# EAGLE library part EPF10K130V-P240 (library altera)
EPF10K130 FLEX 10K family
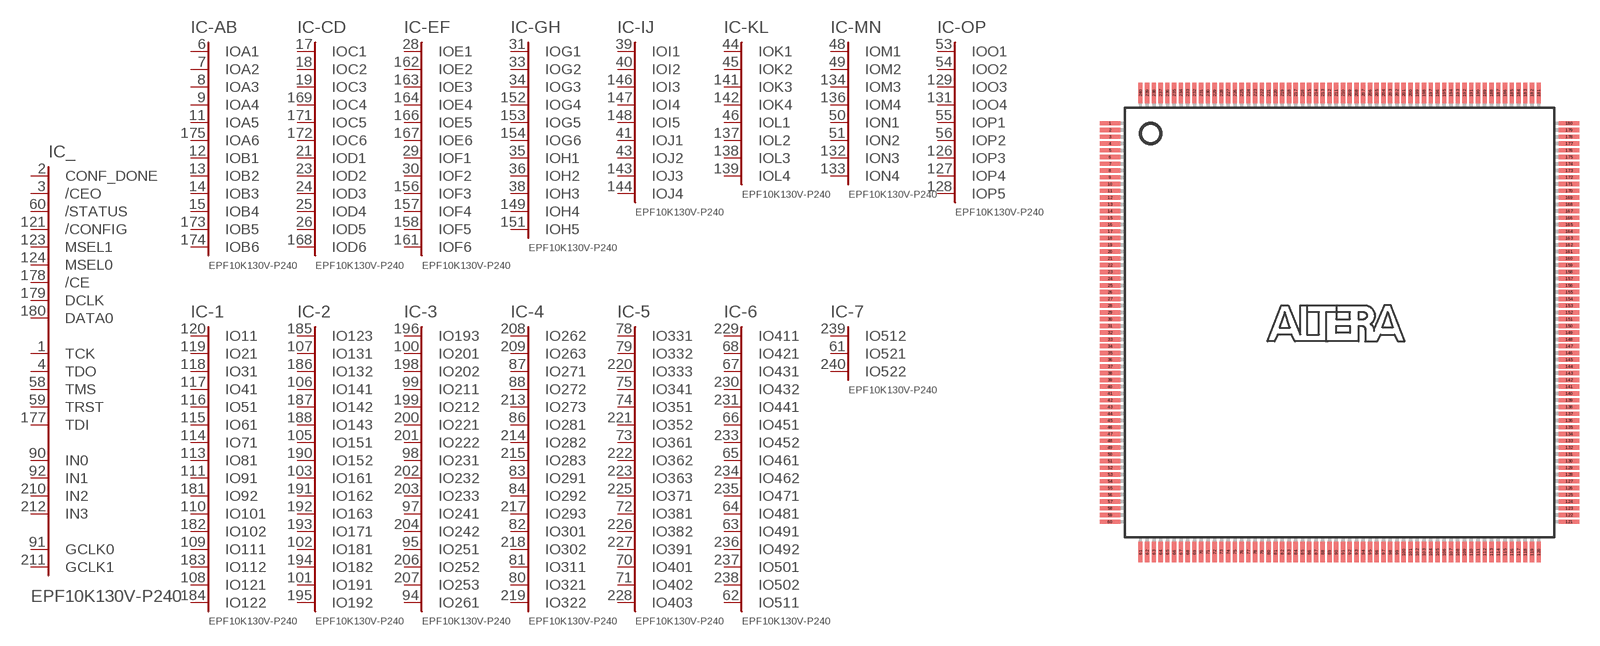
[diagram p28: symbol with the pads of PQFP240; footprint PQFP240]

Designator prefix IC; gates _=K_CTRL -AB=AB6 -CD=CD6 -EF=EF6 -GH=GH6 -IJ=IJ4 -KL=KL4 -MN=MN4 -OP=OP5 -1=122-240 -2=192-240 -3=261-240 -4=322-240 -5=403-240 -6=511-240 -7=522-240 1=VCCINT 2=VCCINT 3=VCCINT 4=VCCINT 5=VCCINT 6=VCCINT 7=VCCINT 8=VCCINT 9=VCCINT 10=VCCINT 11=VCCINT 12=VCCINT 13=VCCIO 14=VCCIO 15=VCCIO 16=VCCIO 17=VCCIO 18=VCCIO 19=VCCIO 20=VCCIO 21=VCCIO 22=VCCIO 23=GND 24=GND 25=GND 26=GND 27=GND 28=GND 29=GND 30=GND 31=GND 32=GND 33=GND 34=GND 35=GND 36=GND 37=GND 38=GND 39=GND 40=GND

## EPF10K130V-P240 (OC_FARNELL: unknown; OC_NEWARK: unknown)  [PQFP240]
1  _:TCK
2  _:CONF_DONE  in
3  _:/CEO  in
4  _:TDO
5  1:VCC  pwr
6  -AB:IOA1
7  -AB:IOA2
8  -AB:IOA3
9  -AB:IOA4
10  23:GND  pwr
11  -AB:IOA5
12  -AB:IOB1
13  -AB:IOB2
14  -AB:IOB3
15  -AB:IOB4
16  13:VCCIO  pwr
17  -CD:IOC1
18  -CD:IOC2
19  -CD:IOC3
20  2:VCC  pwr
21  -CD:IOD1
22  24:GND  pwr
23  -CD:IOD2
24  -CD:IOD3
25  -CD:IOD4
26  -CD:IOD5
27  3:VCC  pwr
28  -EF:IOE1
29  -EF:IOF1
30  -EF:IOF2
31  -GH:IOG1
32  25:GND  pwr
33  -GH:IOG2
34  -GH:IOG3
35  -GH:IOH1
36  -GH:IOH2
37  14:VCCIO  pwr
38  -GH:IOH3
39  -IJ:IOI1
40  -IJ:IOI2
41  -IJ:IOJ1
42  26:GND  pwr
43  -IJ:IOJ2
44  -KL:IOK1
45  -KL:IOK2
46  -KL:IOL1
47  4:VCC  pwr
48  -MN:IOM1
49  -MN:IOM2
50  -MN:ION1
51  -MN:ION2
52  27:GND  pwr
53  -OP:IOO1
54  -OP:IOO2
55  -OP:IOP1
56  -OP:IOP2
57  15:VCCIO  pwr
58  _:TMS
59  _:TRST
60  _:/STATUS  in
61  -7:IO521
62  -6:IO511
63  -6:IO491
64  -6:IO481
65  -6:IO461
66  -6:IO451
67  -6:IO431
68  -6:IO421
69  28:GND  pwr
70  -5:IO401
71  -5:IO402
72  -5:IO381
73  -5:IO361
74  -5:IO351
75  -5:IO341
76  5:VCC  pwr
77  16:VCCIO  pwr
78  -5:IO331
79  -5:IO332
80  -4:IO321
81  -4:IO311
82  -4:IO301
83  -4:IO291
84  -4:IO292
85  29:GND  pwr
86  -4:IO281
87  -4:IO271
88  -4:IO272
89  6:VCC  pwr
90  _:IN0  in
91  _:GCLK0  in
92  _:IN1  in
93  30:GND  pwr
94  -3:IO261
95  -3:IO251
96  7:VCC  pwr
97  -3:IO241
98  -3:IO231
99  -3:IO211
100  -3:IO201
101  -2:IO191
102  -2:IO181
103  -2:IO161
104  31:GND  pwr
105  -2:IO151
106  -2:IO141
107  -2:IO131
108  -1:IO121
109  -1:IO111
110  -1:IO101
111  -1:IO91
112  17:VCCIO  pwr
113  -1:IO81
114  -1:IO71
115  -1:IO61
116  -1:IO51
117  -1:IO41
118  -1:IO31
119  -1:IO21
120  -1:IO11
121  _:/CONFIG  in
122  8:VCC  pwr
123  _:MSEL1  in
124  _:MSEL0  in
125  32:GND  pwr
126  -OP:IOP3
127  -OP:IOP4
128  -OP:IOP5
129  -OP:IOO3
130  9:VCC  pwr
131  -OP:IOO4
132  -MN:ION3
133  -MN:ION4
134  -MN:IOM3
135  33:GND  pwr
136  -MN:IOM4
137  -KL:IOL2
138  -KL:IOL3
139  -KL:IOL4
140  18:VCCIO  pwr
141  -KL:IOK3
142  -KL:IOK4
143  -IJ:IOJ3
144  -IJ:IOJ4
145  34:GND  pwr
146  -IJ:IOI3
147  -IJ:IOI4
148  -IJ:IOI5
149  -GH:IOH4
150  10:VCC  pwr
151  -GH:IOH5
152  -GH:IOG4
153  -GH:IOG5
154  -GH:IOG6
155  35:GND  pwr
156  -EF:IOF3
157  -EF:IOF4
158  -EF:IOF5
159  11:VCC  pwr
160  19:VCCIO  pwr
161  -EF:IOF6
162  -EF:IOE2
163  -EF:IOE3
164  -EF:IOE4
165  36:GND  pwr
166  -EF:IOE5
167  -EF:IOE6
168  -CD:IOD6
169  -CD:IOC4
170  12:VCC  pwr
171  -CD:IOC5
172  -CD:IOC6
173  -AB:IOB5
174  -AB:IOB6
175  -AB:IOA6
176  37:GND  pwr
177  _:TDI
178  _:/CE  in
179  _:DCLK  in
180  _:DATA0  in
181  -1:IO92
182  -1:IO102
183  -1:IO112
184  -1:IO122
185  -2:IO123
186  -2:IO132
187  -2:IO142
188  -2:IO143
189  20:VCCIO  pwr
190  -2:IO152
191  -2:IO162
192  -2:IO163
193  -2:IO171
194  -2:IO182
195  -2:IO192
196  -3:IO193
197  38:GND  pwr
198  -3:IO202
199  -3:IO212
200  -3:IO221
201  -3:IO222
202  -3:IO232
203  -3:IO233
204  -3:IO242
205  21:VCCIO  pwr
206  -3:IO252
207  -3:IO253
208  -4:IO262
209  -4:IO263
210  _:IN2  in
211  _:GCLK1  in
212  _:IN3  in
213  -4:IO273
214  -4:IO282
215  -4:IO283
216  39:GND  pwr
217  -4:IO293
218  -4:IO302
219  -4:IO322
220  -5:IO333
221  -5:IO352
222  -5:IO362
223  -5:IO363
224  22:VCCIO  pwr
225  -5:IO371
226  -5:IO382
227  -5:IO391
228  -5:IO403
229  -6:IO411
230  -6:IO432
231  -6:IO441
232  40:GND  pwr
233  -6:IO452
234  -6:IO462
235  -6:IO471
236  -6:IO492
237  -6:IO501
238  -6:IO502
239  -7:IO512
240  -7:IO522

## Footprint PQFP240 (pad centres in mm)
Plastic Quad Flat Pack
smd 1.5 x 0.32: 1 -17,14.75; 2 -17,14.25; 3 -17,13.75; 4 -17,13.25; 5 -17,12.75; 6 -17,12.25; 7 -17,11.75; 8 -17,11.25; 9 -17,10.75; 10 -17,10.25; 11 -17,9.75; 12 -17,9.25; 13 -17,8.75; 14 -17,8.25; 15 -17,7.75; 16 -17,7.25; 17 -17,6.75; 18 -17,6.25; 19 -17,5.75; 20 -17,5.25; 21 -17,4.75; 22 -17,4.25; 23 -17,3.75; 24 -17,3.25; 25 -17,2.75; 26 -17,2.25; 27 -17,1.75; 28 -17,1.25; 29 -17,0.75; 30 -17,0.25; 31 -17,-0.25; 32 -17,-0.75; 33 -17,-1.25; 34 -17,-1.75; 35 -17,-2.25; 36 -17,-2.75; 37 -17,-3.25; 38 -17,-3.75; 39 -17,-4.25; 40 -17,-4.75; 41 -17,-5.25; 42 -17,-5.75; 43 -17,-6.25; 44 -17,-6.75; 45 -17,-7.25; 46 -17,-7.75; 47 -17,-8.25; 48 -17,-8.75; 49 -17,-9.25; 50 -17,-9.75; 51 -17,-10.25; 52 -17,-10.75; 53 -17,-11.25; 54 -17,-11.75; 55 -17,-12.25; 56 -17,-12.75; 57 -17,-13.25; 58 -17,-13.75; 59 -17,-14.25; 60 -17,-14.75; 121 17,-14.75; 122 17,-14.25; 123 17,-13.75; 124 17,-13.25; 125 17,-12.75; 126 17,-12.25; 127 17,-11.75; 128 17,-11.25; 129 17,-10.75; 130 17,-10.25; 131 17,-9.75; 132 17,-9.25; 133 17,-8.75; 134 17,-8.25; 135 17,-7.75; 136 17,-7.25; 137 17,-6.75; 138 17,-6.25; 139 17,-5.75; 140 17,-5.25; 141 17,-4.75; 142 17,-4.25; 143 17,-3.75; 144 17,-3.25; 145 17,-2.75; 146 17,-2.25; 147 17,-1.75; 148 17,-1.25; 149 17,-0.75; 150 17,-0.25; 151 17,0.25; 152 17,0.75; 153 17,1.25; 154 17,1.75; 155 17,2.25; 156 17,2.75; 157 17,3.25; 158 17,3.75; 159 17,4.25; 160 17,4.75; 161 17,5.25; 162 17,5.75; 163 17,6.25; 164 17,6.75; 165 17,7.25; 166 17,7.75; 167 17,8.25; 168 17,8.75; 169 17,9.25; 170 17,9.75; 171 17,10.25; 172 17,10.75; 173 17,11.25; 174 17,11.75; 175 17,12.25; 176 17,12.75; 177 17,13.25; 178 17,13.75; 179 17,14.25; 180 17,14.75
smd 0.32 x 1.5: 61 -14.75,-17; 62 -14.25,-17; 63 -13.75,-17; 64 -13.25,-17; 65 -12.75,-17; 66 -12.25,-17; 67 -11.75,-17; 68 -11.25,-17; 69 -10.75,-17; 70 -10.25,-17; 71 -9.75,-17; 72 -9.25,-17; 73 -8.75,-17; 74 -8.25,-17; 75 -7.75,-17; 76 -7.25,-17; 77 -6.75,-17; 78 -6.25,-17; 79 -5.75,-17; 80 -5.25,-17; 81 -4.75,-17; 82 -4.25,-17; 83 -3.75,-17; 84 -3.25,-17; 85 -2.75,-17; 86 -2.25,-17; 87 -1.75,-17; 88 -1.25,-17; 89 -0.75,-17; 90 -0.25,-17; 91 0.25,-17; 92 0.75,-17; 93 1.25,-17; 94 1.75,-17; 95 2.25,-17; 96 2.75,-17; 97 3.25,-17; 98 3.75,-17; 99 4.25,-17; 100 4.75,-17; 101 5.25,-17; 102 5.75,-17; 103 6.25,-17; 104 6.75,-17; 105 7.25,-17; 106 7.75,-17; 107 8.25,-17; 108 8.75,-17; 109 9.25,-17; 110 9.75,-17; 111 10.25,-17; 112 10.75,-17; 113 11.25,-17; 114 11.75,-17; 115 12.25,-17; 116 12.75,-17; 117 13.25,-17; 118 13.75,-17; 119 14.25,-17; 120 14.75,-17; 181 14.75,17; 182 14.25,17; 183 13.75,17; 184 13.25,17; 185 12.75,17; 186 12.25,17; 187 11.75,17; 188 11.25,17; 189 10.75,17; 190 10.25,17; 191 9.75,17; 192 9.25,17; 193 8.75,17; 194 8.25,17; 195 7.75,17; 196 7.25,17; 197 6.75,17; 198 6.25,17; 199 5.75,17; 200 5.25,17; 201 4.75,17; 202 4.25,17; 203 3.75,17; 204 3.25,17; 205 2.75,17; 206 2.25,17; 207 1.75,17; 208 1.25,17; 209 0.75,17; 210 0.25,17; 211 -0.25,17; 212 -0.75,17; 213 -1.25,17; 214 -1.75,17; 215 -2.25,17; 216 -2.75,17; 217 -3.25,17; 218 -3.75,17; 219 -4.25,17; 220 -4.75,17; 221 -5.25,17; 222 -5.75,17; 223 -6.25,17; 224 -6.75,17; 225 -7.25,17; 226 -7.75,17; 227 -8.25,17; 228 -8.75,17; 229 -9.25,17; 230 -9.75,17; 231 -10.25,17; 232 -10.75,17; 233 -11.25,17; 234 -11.75,17; 235 -12.25,17; 236 -12.75,17; 237 -13.25,17; 238 -13.75,17; 239 -14.25,17; 240 -14.75,17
